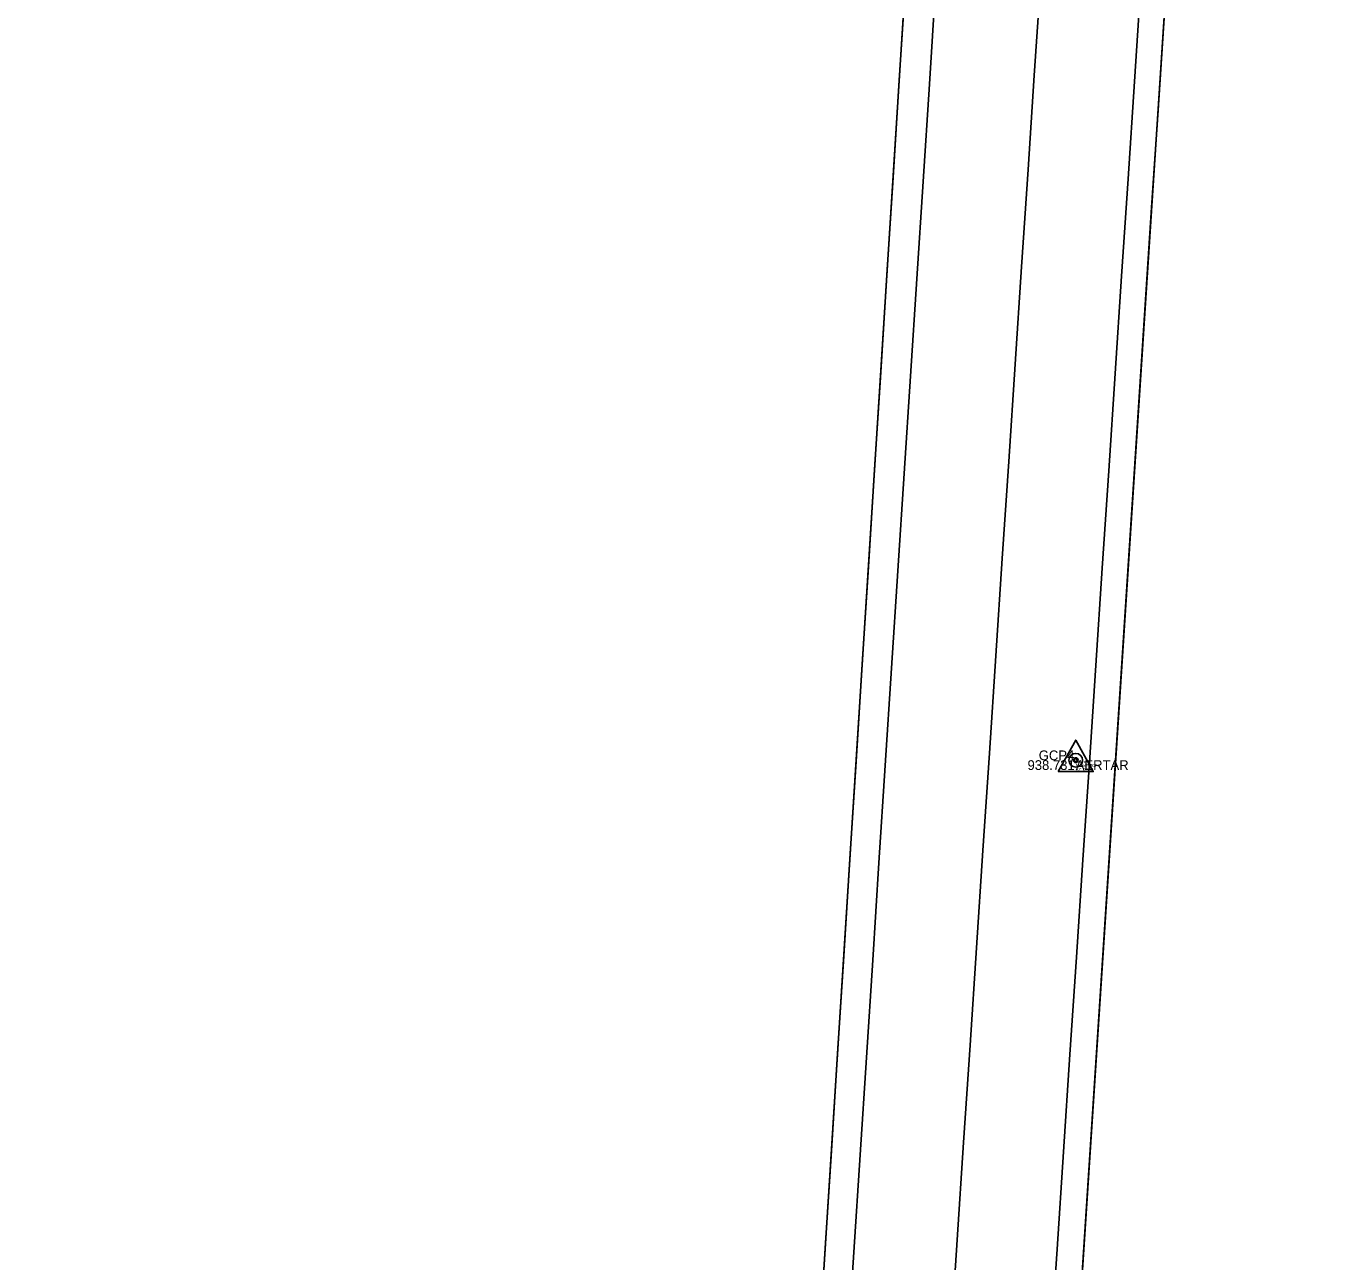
# Model space of a CAD drawing. Extents: x 1988835 to 1989144, y 657973 to 659339.
# Drawn here: x 1988913.5 to 1989047.6, y 658959.8 to 659086.6 of the extents above; entities that cross this region are included whole.
import ezdxf

# ---------------------------------------------------------------- set-up
doc = ezdxf.new("R2010")
doc.units = 0
for name, color, linetype in [('DT_X_Terrain_Boundary', 7, 'Continuous'), ('PM_X_CL_Dashed', 7, 'Continuous'), ('PM_X_CL_Pass_Proh_Rt', 7, 'Continuous'), ('PV_X_EOP', 7, 'Continuous'), ('PV_X_Shoulder_Aggregate', 7, 'Continuous'), ('SV_X_Text_Comment', 7, 'Continuous'), ('SV_X_Text_Elevation', 7, 'Continuous'), ('UT_X_Telecom', 7, 'Continuous'), ('UT_X_Telecom_Cells', 7, 'Continuous')]:
    doc.layers.add(name, color=color, linetype=linetype)

msp = doc.modelspace()

# ---------------------------------------------------------------- linework, layer by layer
at = {"layer": 'DT_X_Terrain_Boundary'}
for points in [[(1989010.62, 659200.77), (1988990.83, 658888.33), (1988990.45, 658882.3), (1988963.36, 658869.89), (1988933.59, 658866.18), (1988913.8, 658868.45), (1988913.53, 658858.66), (1988918.67, 658853.8), (1988958.67, 658853.46), (1988968.57, 658852.58), (1988976.02, 658849.6), (1988979.91, 658847.89), (1988987.83, 658845.23), (1988984.81, 658799.59)], [(1989011.65, 658798.86), (1989014.02, 658836.36), (1989018.64, 658834.4), (1989026.13, 658838.31), (1989045.93, 658835.69), (1989047.59, 658845.55), (1989039.93, 658849.29), (1989030.22, 658851.68), (1989015.7, 658865.14), (1989037.37, 659197.71)]]:
    msp.add_lwpolyline(points, dxfattribs=at)
at = {"layer": 'PM_X_CL_Dashed'}
msp.add_lwpolyline([(1989016.87, 659081.51), (1989017.54, 659091.49), (1989018.2, 659101.46), (1989018.86, 659111.44), (1989019.53, 659121.42), (1989020.19, 659131.4), (1989020.85, 659141.38), (1989021.52, 659151.35), (1989022.18, 659161.33), (1989022.84, 659171.31), (1989023.51, 659181.29), (1989024.17, 659191.26), (1989024.75, 659199.93)], dxfattribs=at)
at = {"layer": 'PM_X_CL_Pass_Proh_Rt'}
msp.add_lwpolyline([(1989008.32, 658952.13), (1989008.98, 658962.11), (1989009.64, 658972.09), (1989010.3, 658982.06), (1989010.96, 658992.04), (1989011.62, 659002.02), (1989012.28, 659012), (1989012.94, 659021.98), (1989013.6, 659031.96), (1989014.26, 659041.93), (1989014.92, 659051.91), (1989015.58, 659061.89), (1989016.24, 659071.87), (1989016.87, 659081.51)], dxfattribs=at)
at = {"layer": 'PV_X_EOP'}
for points in [[(1989006.77, 659090.58), (1989006.13, 659080.6), (1989005.48, 659070.62), (1989004.84, 659060.64), (1989004.19, 659050.66), (1989003.55, 659040.68), (1989002.9, 659030.7), (1989002.26, 659020.72), (1989001.61, 659010.74), (1989000.96, 659000.76), (1989000.32, 658990.78), (1988999.67, 658980.81), (1988999.03, 658970.83), (1988998.38, 658960.85), (1988997.74, 658950.87)], [(1989018.56, 658951.17), (1989019.22, 658961.15), (1989019.88, 658971.13), (1989020.54, 658981.11), (1989021.2, 658991.09), (1989021.86, 659001.06), (1989022.53, 659011.04), (1989023.19, 659021.02), (1989023.85, 659031), (1989024.51, 659040.98), (1989025.17, 659050.95), (1989025.83, 659060.93), (1989026.49, 659070.91), (1989027.15, 659080.89), (1989027.81, 659090.87)]]:
    msp.add_lwpolyline(points, dxfattribs=at)
at = {"layer": 'PV_X_Shoulder_Aggregate'}
for points in [[(1989003.67, 659090.99), (1989003.03, 659081.01), (1989002.4, 659071.03), (1989001.77, 659061.05), (1989001.14, 659051.07), (1989000.51, 659041.09), (1988999.87, 659031.11), (1988999.24, 659021.13), (1988998.61, 659011.15), (1988997.98, 659001.17), (1988997.35, 658991.19), (1988996.71, 658981.21), (1988996.08, 658971.23), (1988995.45, 658961.25), (1988994.82, 658951.27), (1988994.19, 658941.29), (1988993.55, 658931.31), (1988992.92, 658921.33), (1988992.29, 658911.35), (1988991.66, 658901.37), (1988991.03, 658891.39), (1988990.45, 658882.3)], [(1989030.22, 659087.94), (1989029.57, 659077.96), (1989028.91, 659067.98), (1989028.26, 659058), (1989027.61, 659048.02), (1989026.96, 659038.04), (1989026.31, 659028.07), (1989025.66, 659018.09), (1989025.01, 659008.11), (1989024.36, 658998.13), (1989023.71, 658988.15), (1989023.06, 658978.17), (1989022.41, 658968.19), (1989021.76, 658958.21), (1989021.11, 658948.24), (1989020.46, 658938.26), (1989019.81, 658928.28), (1989019.16, 658918.3), (1989018.51, 658908.32), (1989017.86, 658898.34), (1989017.21, 658888.36), (1989016.56, 658878.38), (1989015.91, 658868.4), (1989015.7, 658865.14)]]:
    msp.add_lwpolyline(points, dxfattribs=at)
at = {"layer": 'SV_X_Text_Elevation'}
msp.add_line((1989021.13, 659011.29), (1989021.13, 659011.29), dxfattribs=at)
msp.add_lwpolyline([(1989019.33, 659010.13), (1989022.93, 659010.13), (1989021.13, 659013.35)], close=True, dxfattribs=at)
for radius in [0.7, 0.16]:
    msp.add_circle((1989021.13, 659011.29), radius, dxfattribs=at)
at = {"layer": 'UT_X_Telecom'}
msp.add_line((1989021.13, 659011.29), (1989021.13, 659011.29), dxfattribs=at)
msp.add_circle((1989021.13, 659011.29), 0.25, dxfattribs=at)

# ---------------------------------------------------------------- texts
at = {"layer": 'SV_X_Text_Comment'}
msp.add_text('GCP4', height=1, dxfattribs=at).set_placement((1989017.34, 659011.29))
at = {"layer": 'UT_X_Telecom'}
for s, height, p in [('AERTAR', 1, (1989021.13, 659010.29)), ('Index: 3', 0.3, (1989021.13, 659010.99)), ('ΔZ: 0.086', 0.3, (1989021.13, 659010.19)), ('Name: GCP4', 0.3, (1989021.13, 659010.59))]:
    msp.add_text(s, height=height, dxfattribs=at).set_placement(p)
at = {"layer": 'UT_X_Telecom_Cells'}
msp.add_text('938.731', height=1, dxfattribs=at).set_placement((1989016.19, 659010.29))

doc.saveas('drawing.dxf')
